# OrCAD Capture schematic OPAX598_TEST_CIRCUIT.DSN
size A; title: OPA598 85-V, 250-mA Output Current, Precision, Power Op Amp; rev: 1.0; note: Datasheet: SBOSAA7 - NOV "24  EVM: N/A
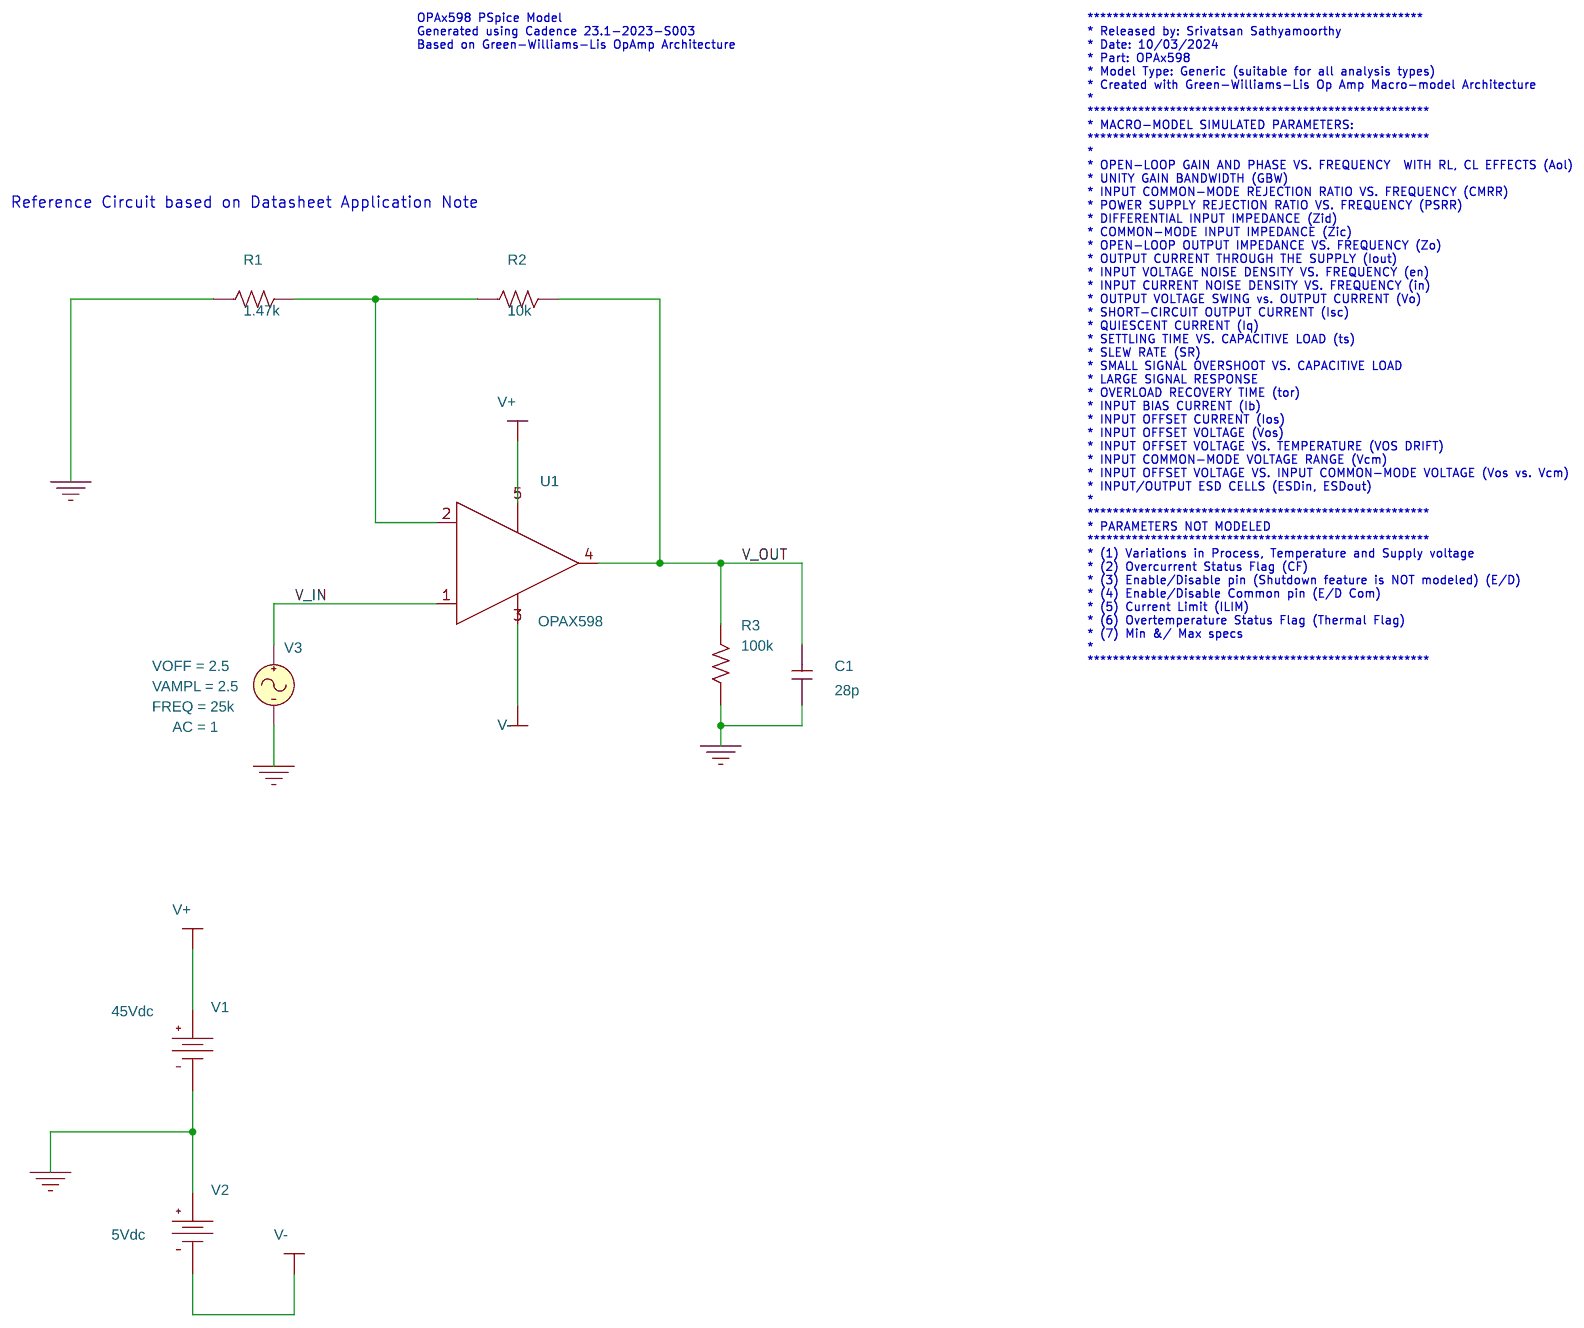
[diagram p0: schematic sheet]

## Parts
C1  28p  [cap196]
R1  1.47k  [AXRC05]
R2  10k  [AXRC05]
R3  100k  [AXRC05]
U1  OPAX598
V1  VDC
V2  VDC
V3  VSIN

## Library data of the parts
C1 = C
R1-R3 = R
U1 = OPAX598
V1 = VDC: DC: 45Vdc
V2 = VDC: DC: 5Vdc
V3 = VSIN: AC: 1; AppProp: Sine$Voltage$0$-1; DC: 0; FREQ: 25k; PHASE: 90; VAMPL: 2.5; VOFF: 2.5

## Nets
0: C1.1 R1.1 R3.1 V1.1(-) V2.0(+) V3.2(-)
V+: U1.5(V+) V1.0(+)
V-: U1.3(V-) V2.1(-)
V_IN: U1.1(+) V3.1(+)
V_OUT: C1.2 R2.2 R3.2 U1.4(OUT)
N02045: R1.2 R2.1 U1.2(-)

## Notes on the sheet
- OPAx598 PSpice Model
  Generated using Cadence 23.1-2023-S003
  Based on Green-Williams-Lis OpAmp Architecture
- *****************************************************
  * Released by: Srivatsan Sathyamoorthy
  * Date: 10/03/2024
  * Part: OPAx598
  * Model Type: Generic (suitable for all analysis types)
  * Created with Green-Williams-Lis Op Amp Macro-model Architecture
  *
  ******************************************************
  * MACRO-MODEL SIMULATED PARAMETERS:
  ******************************************************
  *
  * OPEN-LOOP GAIN AND PHASE VS. FREQUENCY  WITH RL, CL EFFECTS (Aol)
  * UNITY GAIN BANDWIDTH (GBW)
  * INPUT COMMON-MODE REJECTION RATIO VS. FREQUENCY (CMRR)
  * POWER SUPPLY REJECTION RATIO VS. FREQUENCY (PSRR)
  * DIFFERENTIAL INPUT IMPEDANCE (Zid)
  * COMMON-MODE INPUT IMPEDANCE (Zic)
  * OPEN-LOOP OUTPUT IMPEDANCE VS. FREQUENCY (Zo)
  * OUTPUT CURRENT THROUGH THE SUPPLY (Iout)
  * INPUT VOLTAGE NOISE DENSITY VS. FREQUENCY (en)
  * INPUT CURRENT NOISE DENSITY VS. FREQUENCY (in)
  * OUTPUT VOLTAGE SWING vs. OUTPUT CURRENT (Vo)
  * SHORT-CIRCUIT OUTPUT CURRENT (Isc)
  * QUIESCENT CURRENT (Iq)
  * SETTLING TIME VS. CAPACITIVE LOAD (ts)
  * SLEW RATE (SR)
  * SMALL SIGNAL OVERSHOOT VS. CAPACITIVE LOAD
  * LARGE SIGNAL RESPONSE
  * OVERLOAD RECOVERY TIME (tor)
  * INPUT BIAS CURRENT (Ib)
  * INPUT OFFSET CURRENT (Ios)
  * INPUT OFFSET VOLTAGE (Vos)
  * INPUT OFFSET VOLTAGE VS. TEMPERATURE (VOS DRIFT)
  * INPUT COMMON-MODE VOLTAGE RANGE (Vcm)
  * INPUT OFFSET VOLTAGE VS. INPUT COMMON-MODE VOLTAGE (Vos vs. Vcm)
  * INPUT/OUTPUT ESD CELLS (ESDin, ESDout)
  *
  ******************************************************
  * PARAMETERS NOT MODELED
  ******************************************************
  * (1) Variations in Process, Temperature and Supply voltage
  * (2) Overcurrent Status Flag (CF)
  * (3) Enable/Disable pin (Shutdown feature is NOT modeled) (E/D)
  * (4) Enable/Disable Common pin (E/D Com)
  * (5) Current Limit (ILIM)
  * (6) Overtemperature Status Flag (Thermal Flag)
  * (7) Min &/ Max specs
  *
  ******************************************************
- Reference Circuit based on Datasheet Application Note
